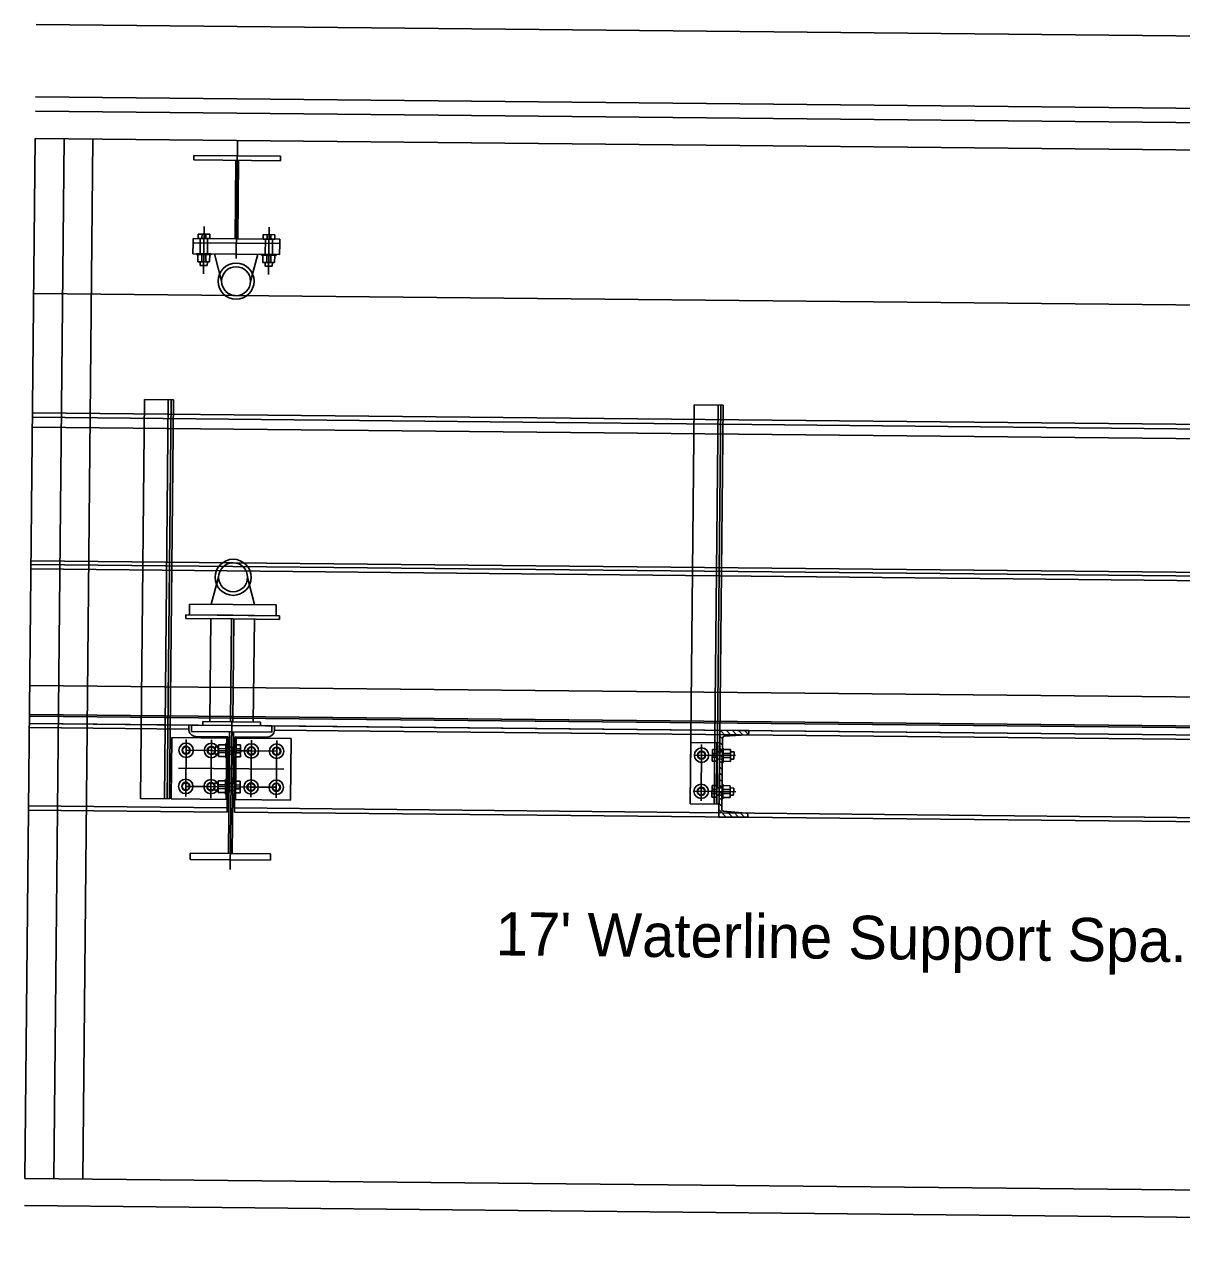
# Model space of a CAD drawing. Extents: x 632312 to 632885, y 378199 to 378534.
# Drawn here: x 632803.35 to 632816.69, y 378305.55 to 378319.72 of the extents above; entities that cross this region are included whole.
import ezdxf

# ---------------------------------------------------------------- set-up
doc = ezdxf.new("R2010")
doc.units = 0
doc.layers.add('SHT_Dimensions', color=7, linetype='Continuous')

msp = doc.modelspace()

# ---------------------------------------------------------------- linework, layer by layer
at = {"layer": 'SHT_Dimensions'}
for p, q in [((632803.483, 378319.72), (632858.169, 378319.176)), ((632803.475, 378318.886), (632858.055, 378318.344)), ((632803.473, 378318.72), (632858.195, 378318.176)), ((632803.47, 378318.407), (632803.351, 378306.408)), ((632803.47, 378318.407), (632858.281, 378317.862)), ((632803.803, 378318.404), (632803.684, 378306.404)), ((632804.137, 378318.4), (632804.018, 378306.401)), ((632805.803, 378318.383), (632805.79, 378317.019)), ((632806.301, 378318.2), (632805.301, 378318.21)), ((632805.301, 378318.21), (632805.301, 378318.159)), ((632806.301, 378318.149), (632805.301, 378318.159)), ((632805.785, 378318.155), (632805.776, 378317.247)), ((632805.817, 378318.154), (632805.808, 378317.247)), ((632806.301, 378318.2), (632806.301, 378318.149)), ((632805.349, 378317.251), (632805.35, 378317.303)), ((632805.485, 378317.302), (632805.35, 378317.303)), ((632805.394, 378317.251), (632805.395, 378317.303)), ((632805.418, 378317.39), (632805.413, 378316.843)), ((632805.439, 378317.25), (632805.44, 378317.303)), ((632805.485, 378317.25), (632805.485, 378317.302)), ((632806.099, 378317.244), (632806.1, 378317.296)), ((632806.235, 378317.295), (632806.1, 378317.296)), ((632806.144, 378317.243), (632806.145, 378317.296)), ((632806.168, 378317.382), (632806.163, 378316.836)), ((632806.189, 378317.243), (632806.19, 378317.295)), ((632806.234, 378317.243), (632806.235, 378317.295)), ((632805.29, 378317.076), (632805.291, 378317.201)), ((632805.291, 378317.201), (632805.292, 378317.252)), ((632805.791, 378317.197), (632805.291, 378317.201)), ((632806.291, 378317.192), (632805.291, 378317.201)), ((632806.292, 378317.242), (632805.292, 378317.252)), ((632805.485, 378317.25), (632805.349, 378317.251)), ((632805.375, 378317.251), (632805.373, 378317.076)), ((632805.459, 378317.25), (632805.457, 378317.075)), ((632805.791, 378317.197), (632806.291, 378317.192)), ((632806.234, 378317.243), (632806.099, 378317.244)), ((632806.125, 378317.244), (632806.123, 378317.068)), ((632806.208, 378317.243), (632806.207, 378317.067)), ((632806.29, 378317.067), (632806.291, 378317.192)), ((632806.291, 378317.192), (632806.292, 378317.242)), ((632805.79, 378317.072), (632805.29, 378317.076)), ((632805.332, 378317.076), (632805.332, 378317.066)), ((632805.498, 378317.074), (632805.332, 378317.076)), ((632805.498, 378317.064), (632805.332, 378317.066)), ((632805.347, 378317.066), (632805.346, 378316.982)), ((632805.392, 378317.065), (632805.392, 378316.982)), ((632805.438, 378317.065), (632805.437, 378316.981)), ((632805.483, 378317.064), (632805.482, 378316.981)), ((632805.498, 378317.074), (632805.498, 378317.064)), ((632805.62, 378316.761), (632805.54, 378317.074)), ((632805.79, 378317.072), (632806.29, 378317.067)), ((632805.954, 378316.757), (632806.04, 378317.069)), ((632806.082, 378317.069), (632806.082, 378317.058)), ((632806.248, 378317.067), (632806.082, 378317.069)), ((632806.248, 378317.057), (632806.082, 378317.058)), ((632806.097, 378317.058), (632806.096, 378316.975)), ((632806.142, 378317.058), (632806.142, 378316.974)), ((632806.188, 378317.057), (632806.187, 378316.974)), ((632806.233, 378317.057), (632806.232, 378316.973)), ((632806.248, 378317.067), (632806.248, 378317.057)), ((632805.482, 378316.981), (632805.346, 378316.982)), ((632805.372, 378316.982), (632805.372, 378316.94)), ((632805.455, 378316.939), (632805.372, 378316.94)), ((632805.456, 378316.981), (632805.455, 378316.939)), ((632806.232, 378316.973), (632806.096, 378316.975)), ((632806.122, 378316.974), (632806.122, 378316.933)), ((632806.205, 378316.932), (632806.122, 378316.933)), ((632806.206, 378316.974), (632806.205, 378316.932)), ((632858.298, 378316.07), (632803.452, 378316.616)), ((632804.685, 378310.79), (632804.73, 378315.394)), ((632805.064, 378315.391), (632804.73, 378315.394)), ((632804.961, 378310.788), (632805.006, 378315.392)), ((632804.992, 378310.787), (632805.038, 378315.391)), ((632805.018, 378310.787), (632805.064, 378315.391)), ((632811.025, 378310.73), (632811.071, 378315.334)), ((632811.404, 378315.33), (632811.071, 378315.334)), ((632811.301, 378310.727), (632811.347, 378315.331)), ((632811.333, 378310.727), (632811.378, 378315.331)), ((632811.359, 378310.726), (632811.404, 378315.33)), ((632803.438, 378315.189), (632857.879, 378314.647)), ((632803.439, 378315.241), (632857.859, 378314.7)), ((632858.496, 378314.527), (632803.437, 378315.074)), ((632803.421, 378313.491), (632857.782, 378312.95)), ((632857.708, 378312.993), (632803.422, 378313.532)), ((632803.421, 378313.439), (632857.788, 378312.898)), ((632805.586, 378313.344), (632805.5, 378313.033)), ((632805.92, 378313.341), (632806, 378313.028)), ((632805.207, 378312.869), (632805.207, 378312.91)), ((632805.207, 378312.91), (632806.29, 378312.9)), ((632805.25, 378313.035), (632805.249, 378312.91)), ((632805.749, 378312.905), (632805.249, 378312.91)), ((632805.75, 378313.03), (632805.25, 378313.035)), ((632805.749, 378312.905), (632806.249, 378312.9)), ((632805.75, 378313.03), (632806.25, 378313.025)), ((632806.25, 378313.025), (632806.249, 378312.9)), ((632806.29, 378312.858), (632806.29, 378312.9)), ((632805.748, 378312.863), (632805.207, 378312.869)), ((632805.486, 378311.678), (632805.498, 378312.866)), ((632805.724, 378311.676), (632805.736, 378312.863)), ((632805.748, 378312.863), (632806.29, 378312.858)), ((632805.761, 378312.863), (632805.749, 378311.676)), ((632805.986, 378311.673), (632805.998, 378312.861)), ((632803.407, 378312.095), (632857.654, 378311.556)), ((632803.403, 378311.657), (632853.734, 378311.157)), ((632805.242, 378311.639), (632803.403, 378311.657)), ((632803.404, 378311.762), (632857.65, 378311.222)), ((632803.404, 378311.741), (632857.65, 378311.201)), ((632805.242, 378311.639), (632805.242, 378311.591)), ((632805.274, 378311.639), (632805.273, 378311.566)), ((632806.198, 378311.63), (632805.274, 378311.639)), ((632805.403, 378311.638), (632805.403, 378311.679)), ((632805.403, 378311.679), (632806.07, 378311.673)), ((632805.486, 378311.678), (632805.986, 378311.673)), ((632805.719, 378309.972), (632805.737, 378311.686)), ((632806.069, 378311.631), (632806.07, 378311.673)), ((632806.198, 378311.63), (632806.198, 378311.557)), ((632806.23, 378311.629), (632806.229, 378311.581)), ((632806.23, 378311.629), (632807.316, 378311.619)), ((632805.242, 378311.591), (632803.403, 378311.61)), ((632805.039, 378310.787), (632805.046, 378311.495)), ((632805.712, 378311.489), (632805.046, 378311.495)), ((632806.198, 378311.557), (632805.273, 378311.566)), ((632805.324, 378311.507), (632805.692, 378311.503)), ((632805.674, 378310.781), (632805.681, 378311.489)), ((632805.683, 378310.635), (632805.692, 378311.503)), ((632805.699, 378310.157), (632805.713, 378311.562)), ((632805.705, 378310.78), (632805.712, 378311.489)), ((632805.758, 378311.562), (632805.744, 378310.157)), ((632805.75, 378310.78), (632805.757, 378311.488)), ((632805.757, 378311.488), (632806.423, 378311.482)), ((632805.778, 378311.503), (632805.769, 378310.634)), ((632806.145, 378311.499), (632805.778, 378311.503)), ((632805.781, 378310.78), (632805.788, 378311.488)), ((632806.229, 378311.581), (632807.332, 378311.57)), ((632806.416, 378310.773), (632806.423, 378311.482)), ((632822.241, 378311.47), (632807.316, 378311.619)), ((632822.241, 378311.422), (632807.332, 378311.57)), ((632811.367, 378311.578), (632811.357, 378310.578)), ((632811.397, 378311.479), (632811.366, 378311.51)), ((632811.367, 378311.578), (632811.7, 378311.575)), ((632811.436, 378311.51), (632811.369, 378311.578)), ((632811.397, 378311.488), (632811.389, 378310.668)), ((632811.402, 378311.578), (632811.402, 378311.576)), ((632811.418, 378311.509), (632811.679, 378311.527)), ((632811.502, 378311.515), (632811.44, 378311.578)), ((632811.567, 378311.519), (632811.511, 378311.577)), ((632811.633, 378311.524), (632811.582, 378311.576)), ((632811.694, 378311.533), (632811.652, 378311.575)), ((632811.7, 378311.575), (632811.7, 378311.548)), ((632805.212, 378311.471), (632805.206, 378310.816)), ((632805.211, 378311.348), (632805.502, 378311.345)), ((632805.504, 378311.468), (632805.497, 378310.797)), ((632805.502, 378311.345), (632805.733, 378311.343)), ((632805.545, 378311.386), (632805.544, 378311.303)), ((632805.586, 378311.386), (632805.545, 378311.386)), ((632805.586, 378311.412), (632805.585, 378311.276)), ((632805.67, 378311.411), (632805.586, 378311.412)), ((632805.669, 378311.366), (632805.586, 378311.367)), ((632805.67, 378311.427), (632805.668, 378311.26)), ((632805.68, 378311.426), (632805.67, 378311.427)), ((632805.68, 378311.426), (632805.679, 378311.26)), ((632805.787, 378311.384), (632805.68, 378311.385)), ((632805.964, 378311.34), (632805.733, 378311.343)), ((632805.787, 378311.41), (632805.786, 378311.274)), ((632805.787, 378311.41), (632805.839, 378311.409)), ((632805.787, 378311.365), (632805.839, 378311.364)), ((632805.839, 378311.409), (632805.838, 378311.274)), ((632805.965, 378311.463), (632805.958, 378310.807)), ((632806.255, 378311.337), (632805.964, 378311.34)), ((632806.257, 378311.46), (632806.25, 378310.801)), ((632811.032, 378311.438), (632811.025, 378310.73)), ((632811.032, 378311.438), (632811.366, 378311.435)), ((632811.157, 378311.414), (632811.151, 378310.766)), ((632811.281, 378311.357), (632811.28, 378311.222)), ((632811.334, 378311.357), (632811.281, 378311.357)), ((632811.327, 378310.727), (632811.334, 378311.435)), ((632811.334, 378311.357), (632811.332, 378311.222)), ((632811.359, 378310.726), (632811.366, 378311.435)), ((632811.395, 378311.337), (632811.365, 378311.369)), ((632811.396, 378311.408), (632811.366, 378311.439)), ((632811.396, 378311.372), (632811.394, 378311.205)), ((632811.396, 378311.372), (632811.406, 378311.372)), ((632811.406, 378311.372), (632811.405, 378311.205)), ((632811.406, 378311.356), (632811.489, 378311.355)), ((632811.489, 378311.355), (632811.488, 378311.22)), ((632805.585, 378311.302), (632805.544, 378311.303)), ((632805.668, 378311.276), (632805.585, 378311.276)), ((632805.669, 378311.321), (632805.586, 378311.321)), ((632805.679, 378311.26), (632805.668, 378311.26)), ((632805.786, 378311.3), (632805.679, 378311.301)), ((632805.786, 378311.319), (632805.839, 378311.319)), ((632805.786, 378311.274), (632805.838, 378311.274)), ((632811.073, 378311.292), (632811.547, 378311.287)), ((632811.332, 378311.222), (632811.28, 378311.222)), ((632811.333, 378311.312), (632811.281, 378311.312)), ((632811.333, 378311.267), (632811.281, 378311.267)), ((632811.332, 378311.248), (632811.395, 378311.247)), ((632811.333, 378311.331), (632811.395, 378311.33)), ((632811.395, 378311.267), (632811.364, 378311.298)), ((632811.394, 378311.196), (632811.364, 378311.227)), ((632811.394, 378311.205), (632811.405, 378311.205)), ((632811.405, 378311.266), (632811.488, 378311.265)), ((632811.405, 378311.221), (632811.488, 378311.22)), ((632811.406, 378311.311), (632811.489, 378311.31)), ((632811.488, 378311.246), (632811.53, 378311.246)), ((632811.489, 378311.329), (632811.531, 378311.329)), ((632811.531, 378311.329), (632811.53, 378311.246)), ((632806.337, 378311.128), (632805.125, 378311.14)), ((632811.393, 378311.055), (632811.362, 378311.086)), ((632811.393, 378311.125), (632811.363, 378311.156)), ((632805.207, 378310.931), (632805.498, 378310.928)), ((632805.498, 378310.928), (632805.729, 378310.926)), ((632805.54, 378310.969), (632805.54, 378310.886)), ((632805.582, 378310.969), (632805.54, 378310.969)), ((632805.582, 378310.995), (632805.581, 378310.86)), ((632805.666, 378310.994), (632805.582, 378310.995)), ((632805.665, 378310.949), (632805.582, 378310.95)), ((632805.666, 378311.01), (632805.664, 378310.843)), ((632805.676, 378311.01), (632805.666, 378311.01)), ((632805.676, 378311.01), (632805.675, 378310.843)), ((632805.783, 378310.967), (632805.676, 378310.968)), ((632805.96, 378310.924), (632805.729, 378310.926)), ((632805.783, 378310.993), (632805.782, 378310.858)), ((632805.783, 378310.993), (632805.835, 378310.993)), ((632805.783, 378310.948), (632805.835, 378310.947)), ((632805.835, 378310.993), (632805.834, 378310.857)), ((632806.251, 378310.921), (632805.96, 378310.924)), ((632811.277, 378310.941), (632811.276, 378310.805)), ((632811.329, 378310.94), (632811.277, 378310.941)), ((632811.329, 378310.94), (632811.328, 378310.805)), ((632811.392, 378310.984), (632811.361, 378311.015)), ((632811.391, 378310.913), (632811.361, 378310.944)), ((632811.392, 378310.955), (632811.39, 378310.789)), ((632811.392, 378310.955), (632811.402, 378310.955)), ((632811.402, 378310.955), (632811.4, 378310.789)), ((632811.402, 378310.94), (632811.485, 378310.939)), ((632811.485, 378310.939), (632811.484, 378310.803)), ((632804.685, 378310.79), (632805.018, 378310.787)), ((632805.039, 378310.787), (632805.705, 378310.78)), ((632805.581, 378310.886), (632805.54, 378310.886)), ((632805.665, 378310.904), (632805.581, 378310.905)), ((632805.664, 378310.859), (632805.581, 378310.86)), ((632805.675, 378310.843), (632805.664, 378310.843)), ((632805.782, 378310.884), (632805.675, 378310.885)), ((632806.416, 378310.773), (632805.75, 378310.78)), ((632805.782, 378310.903), (632805.834, 378310.902)), ((632805.782, 378310.858), (632805.834, 378310.857)), ((632811.068, 378310.875), (632811.55, 378310.87)), ((632811.329, 378310.85), (632811.276, 378310.851)), ((632811.328, 378310.805), (632811.276, 378310.805)), ((632811.329, 378310.895), (632811.277, 378310.896)), ((632811.328, 378310.831), (632811.39, 378310.83)), ((632811.329, 378310.914), (632811.391, 378310.914)), ((632811.39, 378310.772), (632811.359, 378310.803)), ((632811.391, 378310.843), (632811.36, 378310.874)), ((632811.39, 378310.789), (632811.4, 378310.789)), ((632811.401, 378310.894), (632811.485, 378310.894)), ((632811.401, 378310.849), (632811.484, 378310.849)), ((632811.401, 378310.804), (632811.484, 378310.803)), ((632811.484, 378310.829), (632811.526, 378310.829)), ((632811.485, 378310.913), (632811.527, 378310.912)), ((632811.527, 378310.912), (632811.526, 378310.829)), ((632803.393, 378310.657), (632804.145, 378310.65)), ((632803.394, 378310.705), (632804.145, 378310.698)), ((632805.683, 378310.683), (632804.145, 378310.698)), ((632805.683, 378310.635), (632804.145, 378310.65)), ((632805.769, 378310.634), (632821.144, 378310.481)), ((632805.77, 378310.682), (632821.145, 378310.529)), ((632811.025, 378310.73), (632811.359, 378310.726)), ((632811.025, 378310.73), (632811.359, 378310.726)), ((632811.44, 378310.577), (632811.358, 378310.662)), ((632811.389, 378310.701), (632811.359, 378310.732)), ((632811.409, 378310.647), (632811.67, 378310.623)), ((632811.511, 378310.577), (632811.446, 378310.643)), ((632811.582, 378310.576), (632811.523, 378310.636)), ((632811.37, 378310.578), (632811.357, 378310.591)), ((632811.36, 378310.578), (632811.357, 378310.581)), ((632811.357, 378310.578), (632811.69, 378310.575)), ((632811.357, 378310.578), (632811.69, 378310.575)), ((632811.652, 378310.575), (632811.599, 378310.629)), ((632811.69, 378310.609), (632811.677, 378310.622)), ((632811.69, 378310.575), (632811.691, 378310.602)), ((632805.258, 378310.089), (632805.259, 378310.161)), ((632806.183, 378310.08), (632805.258, 378310.089)), ((632806.184, 378310.152), (632805.259, 378310.161)), ((632806.183, 378310.08), (632806.184, 378310.152)), ((632803.351, 378306.408), (632857.672, 378305.868)), ((632803.348, 378306.095), (632857.7, 378305.555))]:
    msp.add_line(p, q, dxfattribs=at)
for centre, radius in [((632805.787, 378316.759), 0.208), ((632805.787, 378316.759), 0.167), ((632805.753, 378313.343), 0.208), ((632805.753, 378313.343), 0.167), ((632805.211, 378311.348), 0.0833), ((632805.211, 378311.348), 0.0469), ((632805.211, 378311.348), 0.0417), ((632805.502, 378311.345), 0.0833), ((632805.502, 378311.345), 0.0469), ((632805.502, 378311.345), 0.0417), ((632805.964, 378311.34), 0.0833), ((632805.964, 378311.34), 0.0469), ((632805.964, 378311.34), 0.0417), ((632806.255, 378311.337), 0.0833), ((632806.255, 378311.337), 0.0469), ((632806.255, 378311.337), 0.0417), ((632811.156, 378311.291), 0.0833), ((632811.156, 378311.291), 0.0469), ((632811.156, 378311.291), 0.0417), ((632805.207, 378310.931), 0.0833), ((632805.207, 378310.931), 0.0469), ((632805.207, 378310.931), 0.0417), ((632805.498, 378310.928), 0.0833), ((632805.498, 378310.928), 0.0469), ((632805.498, 378310.928), 0.0417), ((632805.96, 378310.924), 0.0833), ((632805.96, 378310.924), 0.0469), ((632805.96, 378310.924), 0.0417), ((632806.251, 378310.921), 0.0833), ((632806.251, 378310.921), 0.0469), ((632806.251, 378310.921), 0.0417), ((632811.152, 378310.874), 0.0833), ((632811.152, 378310.874), 0.0469), ((632811.152, 378310.874), 0.0417)]:
    msp.add_circle(centre, radius, dxfattribs=at)
for centre, radius, start, end in [((632805.325, 378311.59), 0.0833, 179.4304, 269.4304), ((632806.146, 378311.582), 0.0833, 269.4304, 359.4304), ((632811.418, 378311.488), 0.0208, 89.4304, 179.4304), ((632811.679, 378311.548), 0.0208, 269.4304, 359.4388), ((632811.41, 378310.667), 0.0208, 179.4304, 269.4304), ((632811.67, 378310.602), 0.0208, 359.4304, 89.4304)]:
    msp.add_arc(centre, radius, start, end, dxfattribs=at)

# ---------------------------------------------------------------- texts
msp.add_text("17' Waterline Support Spa.", height=0.5, rotation=359.4304, dxfattribs=at).set_placement((632808.78, 378308.982))

doc.saveas('drawing.dxf')
